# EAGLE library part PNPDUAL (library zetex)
Dual PNP TRANSISTOR
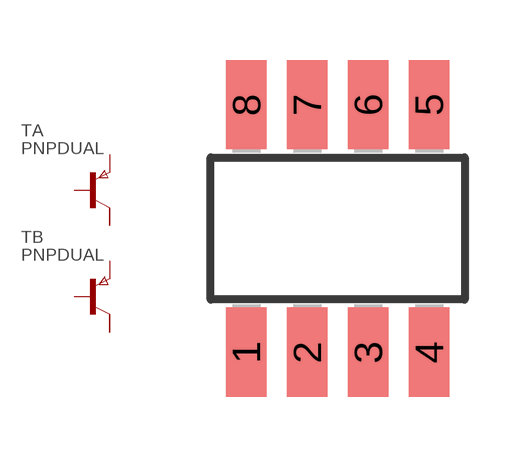
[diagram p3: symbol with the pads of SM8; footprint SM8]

Designator prefix T; gates A=PNP2C B=PNP2C

## PNPDUAL (OC_FARNELL: unknown; OC_NEWARK: unknown)  [SM8]
1  B:E  pas
2  B:B  pas
3  A:E  pas
4  A:B  pas
5  B:C  pas
6  B:C1  pas
7  A:C  pas
8  A:C1  pas

## Footprint SM8 (pad centres in mm)
SM8 Package
smd 1.016 x 2.235: 1 -2.286,-3.099; 2 -0.762,-3.099; 3 0.762,-3.099; 4 2.286,-3.099; 5 2.286,3.099; 6 0.762,3.099; 7 -0.762,3.099; 8 -2.286,3.099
